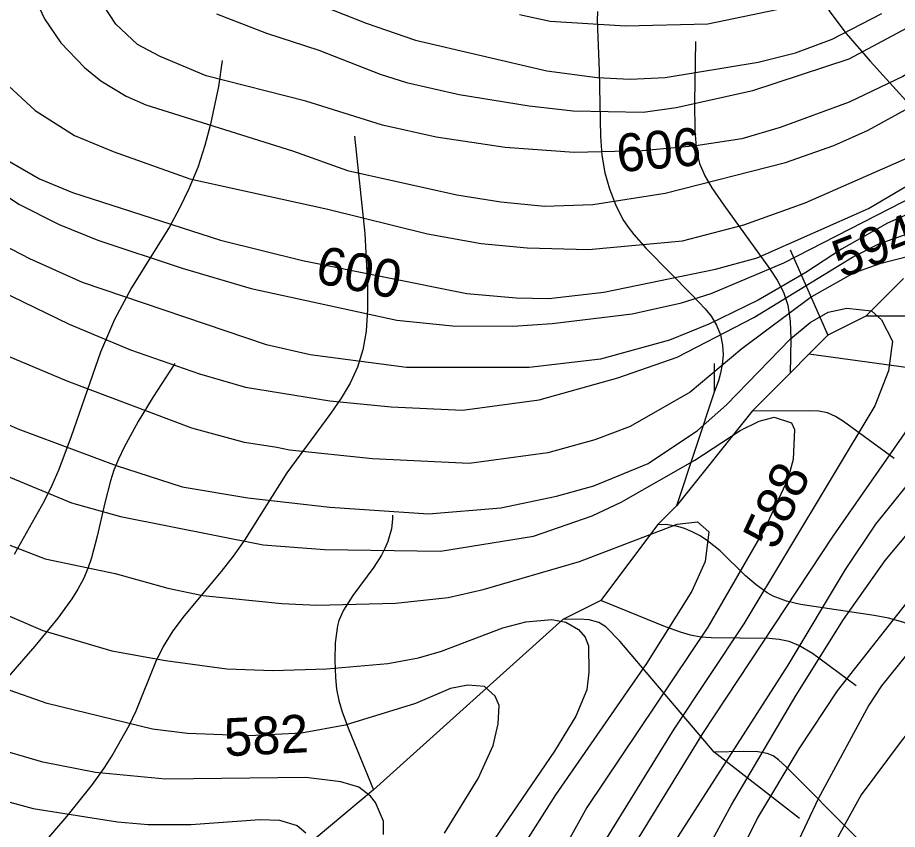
# Model space of a CAD drawing. Extents: x -709584 to -702006, y -1161789 to -1157496.
# Drawn here: x -708901 to -708668.6, y -1161172.4 to -1160958.2 of the extents above; entities that cross this region are included whole.
import ezdxf

# ---------------------------------------------------------------- set-up
doc = ezdxf.new("R2010")
doc.units = 0
for name, color, linetype in [('120_vrstevnice hlavní', 7, 'Continuous'), ('121_vrstevnice hlavní_popis', 7, 'Continuous'), ('122_vrstevnice základní', 7, 'Continuous'), ('411_akumulovaný odtok', 7, 'Continuous')]:
    doc.layers.add(name, color=color, linetype=linetype)

msp = doc.modelspace()

# ---------------------------------------------------------------- linework, layer by layer
at = {"layer": '120_vrstevnice hlavní'}
for points in [[(-708826.33, -1160952.72), (-708808.97, -1160959.66), (-708795.95, -1160964.15), (-708761.23, -1160972.25), (-708747.93, -1160973.98), (-708739.25, -1160974.41), (-708729.99, -1160973.98), (-708705.4, -1160969.93), (-708695.57, -1160967.47), (-708685.88, -1160963.86), (-708672.71, -1160957.06)], [(-708908.19, -1160993.22), (-708895.18, -1161000.74), (-708886.5, -1161004.36), (-708847.44, -1161016.94), (-708825.75, -1161022.29), (-708782.35, -1161030.97), (-708769.33, -1161032.13), (-708760.66, -1161032.27), (-708746.19, -1161030.68), (-708716.68, -1161024.61), (-708705.69, -1161021.57), (-708676.28, -1161008.53), (-708657.13, -1160997.28)], [(-708840.21, -1161084.92), (-708818.51, -1161087.38), (-708792.48, -1161089.12), (-708773.39, -1161087.53), (-708758.63, -1161084.49), (-708748.8, -1161081.74), (-708734.48, -1161075.81), (-708721.46, -1161067.13), (-708713.79, -1161060.33), (-708696.87, -1161042.98), (-708691.66, -1161038.64), (-708686.89, -1161035.89), (-708681.97, -1161034.88), (-708675.46, -1161035.6), (-708672.86, -1161037.91), (-708669.96, -1161043.55), (-708670.98, -1161051.36), (-708674.59, -1161060.62), (-708709.16, -1161118.19), (-708727.68, -1161145.96), (-708756.32, -1161192.25)], [(-708913.98, -1161060.91), (-708900.96, -1161066.7), (-708874.93, -1161076.39), (-708857.57, -1161082.03), (-708840.21, -1161084.92)], [(-708659.26, -1161117.76), (-708672.86, -1161134.54), (-708676.18, -1161139.6), (-708689.54, -1161164.31), (-708704.1, -1161195.14)], [(-708804.34, -1161173.73), (-708804.34, -1161170.26), (-708806.51, -1161165.34), (-708807.81, -1161163.61), (-708810.85, -1161161.29), (-708815.62, -1161159.85), (-708824.88, -1161158.69), (-708861.91, -1161159.12), (-708880.42, -1161157.39), (-708894.31, -1161154.64), (-708908.19, -1161150.59)]]:
    msp.add_lwpolyline(points, dxfattribs=at)
at = {"layer": '122_vrstevnice základní'}
for points in [[(-708621.94, -1160943.75), (-708641.76, -1160958.5), (-708667.22, -1160973.69), (-708681.39, -1160980.49), (-708699.62, -1160987.14), (-708709.74, -1160990.18), (-708721.89, -1160992.06), (-708736.07, -1160993.36), (-708754, -1160993.8), (-708772.23, -1160992.5), (-708790.45, -1160989.75), (-708804.63, -1160986.56), (-708824.88, -1160980.2), (-708851.2, -1160973.55), (-708863.35, -1160968.48), (-708869.28, -1160965.3), (-708875.07, -1160959.95), (-708878.25, -1160955.03)], [(-708848.46, -1160957.2), (-708835.29, -1160962.26), (-708821.41, -1160966.75), (-708805.21, -1160973.11), (-708798.26, -1160975.28), (-708784.38, -1160978.46), (-708765.86, -1160981.5), (-708754.29, -1160982.8), (-708735.78, -1160983.09), (-708727.1, -1160981.94), (-708706.85, -1160977.45), (-708681.39, -1160969.06), (-708661.14, -1160958.21), (-708639.16, -1160944.04)], [(-708896.77, -1160952.14), (-708893.87, -1160958.5), (-708889.53, -1160964.87), (-708883.32, -1160971.38), (-708878.98, -1160974.85), (-708872.32, -1160978.9), (-708867.12, -1160981.21), (-708828.35, -1160993.36), (-708813.89, -1160998.57), (-708784.96, -1161004.93), (-708773.39, -1161006.81), (-708761.81, -1161007.97), (-708749.08, -1161007.54), (-708729.99, -1161004.5), (-708698.17, -1160996.4), (-708685.44, -1160991.92), (-708676.33, -1160987.87), (-708659.55, -1160978.61), (-708645.23, -1160969.35), (-708624.69, -1160957.35)], [(-708903.42, -1160976.15), (-708896.33, -1160982.66), (-708885.92, -1160989.31), (-708875.79, -1160993.51), (-708855.54, -1161000.74), (-708819.09, -1161008.7), (-708792.77, -1161015.2), (-708778.59, -1161017.81), (-708766.44, -1161018.97), (-708750.24, -1161019.4), (-708725.36, -1161017.08), (-708709.16, -1161012.89), (-708692.96, -1161007.1), (-708666.78, -1160995.53), (-708647.4, -1160984.54), (-708610.52, -1160959.23), (-708602.42, -1160955.18)], [(-708768.47, -1160957.35), (-708760.37, -1160959.08), (-708740.41, -1160960.38), (-708718.71, -1160959.8), (-708700.48, -1160956.04)], [(-708575.95, -1160956.77), (-708574.21, -1160959.08), (-708572.04, -1160963.71), (-708571.03, -1160975.28), (-708573.34, -1160993.8), (-708581.44, -1161030.83), (-708586.5, -1161047.03), (-708593.59, -1161059.18), (-708599.09, -1161066.84), (-708615.72, -1161087.38), (-708651.16, -1161128.61), (-708667.62, -1161149.13), (-708678.21, -1161163.32), (-708687.61, -1161180.39)], [(-708889.97, -1161012.75), (-708879.84, -1161016.94), (-708857.57, -1161024.32), (-708839.34, -1161029.67), (-708800.87, -1161038.06), (-708786.11, -1161039.5), (-708770.2, -1161039.65), (-708759.79, -1161038.93), (-708738.67, -1161036.32), (-708725.65, -1161033.43), (-708717.84, -1161030.97), (-708698.6, -1161022.87), (-708635.97, -1160990.76)], [(-708917.02, -1160996.4), (-708900.67, -1161007.39), (-708889.97, -1161012.75)], [(-708644.07, -1161000.45), (-708671.27, -1161012.46), (-708683.42, -1161019.25), (-708692.82, -1161025.47), (-708705.4, -1161032.71), (-708718.42, -1161039.07), (-708728.83, -1161043.27), (-708747.06, -1161048.33), (-708765.86, -1161050.5), (-708798.26, -1161050.5), (-708823.72, -1161047.17), (-708835.29, -1161044.57), (-708883.89, -1161028.08), (-708897.78, -1161021.86), (-708913.98, -1161013.47)], [(-708887.37, -1161039.07), (-708871.17, -1161045.87), (-708852.94, -1161052.23), (-708840.79, -1161055.71), (-708818.51, -1161059.32), (-708802.31, -1161060.91), (-708783.51, -1161061.78), (-708763.26, -1161059.03), (-708742.43, -1161053.25), (-708726.81, -1161047.75), (-708706.56, -1161037.33), (-708680.52, -1161021.42), (-708673.73, -1161017.95), (-708658.54, -1161012.6)], [(-708665.34, -1161021.13), (-708673.29, -1161023.16), (-708680.23, -1161025.62), (-708691.37, -1161031.84), (-708709.74, -1161045.58), (-708723.34, -1161057.01), (-708739.25, -1161066.12), (-708748.51, -1161069.59), (-708760.95, -1161073.06), (-708781.77, -1161075.81), (-708807.23, -1161074.65), (-708829.22, -1161072.34), (-708832.54, -1161071.62), (-708841.08, -1161070.31), (-708854.96, -1161066.55), (-708887.94, -1161054.11), (-708922.66, -1161039.5)], [(-708908.63, -1161028.8), (-708887.37, -1161039.07)], [(-708685.58, -1161095.05), (-708653.19, -1161048.62)], [(-708953.18, -1161051.8), (-708934.52, -1161064.96), (-708925.84, -1161070.02), (-708886.79, -1161086.22), (-708873.77, -1161089.84), (-708836.16, -1161097.36), (-708819.96, -1161098.52), (-708789.3, -1161098.95), (-708764.71, -1161095.05), (-708749.23, -1161089.7), (-708741.56, -1161086.08), (-708722.18, -1161074.94), (-708710.18, -1161067.13), (-708705.11, -1161064.67), (-708701.21, -1161063.66), (-708696.58, -1161065.11), (-708695.86, -1161066.84), (-708696.15, -1161074.8), (-708697.59, -1161080.01), (-708703.67, -1161093.02), (-708718.71, -1161119.06), (-708750.68, -1161166.65), (-708757.04, -1161178.07)], [(-708723.48, -1161186.17), (-708712.49, -1161165.92), (-708695.42, -1161137), (-708682.84, -1161117.03), (-708671.84, -1161101.41), (-708643.93, -1161068.14), (-708634.24, -1161055.13)], [(-708646.82, -1161057.58), (-708674.45, -1161091.86), (-708682.4, -1161103.87), (-708697.59, -1161129.04), (-708733.32, -1161184.73)], [(-708905.88, -1161096.35), (-708893.73, -1161100.98), (-708875.21, -1161104.88), (-708861.33, -1161108.79), (-708852.07, -1161110.67), (-708831.24, -1161112.84), (-708821.99, -1161113.27), (-708801.16, -1161112.7), (-708787.27, -1161111.25), (-708778.01, -1161109.08), (-708752.56, -1161101.7), (-708726.81, -1161091.87), (-708721.46, -1161091.29), (-708718.42, -1161093.89), (-708719.43, -1161101.7), (-708722.9, -1161109.51), (-708734.91, -1161128.61), (-708758.92, -1161163.32), (-708781.05, -1161198.03)], [(-708739.25, -1161178.36), (-708720.01, -1161147.12), (-708685.58, -1161095.05)], [(-708931.05, -1161104.16), (-708894.31, -1161119.93), (-708876.08, -1161125.28), (-708861.91, -1161127.88), (-708845.71, -1161130.05), (-708833.56, -1161130.49), (-708819.38, -1161130.05), (-708803.18, -1161128.61), (-708795.08, -1161127.16), (-708789.01, -1161125.42), (-708772.81, -1161119.2), (-708766.73, -1161117.61), (-708759.93, -1161117.03), (-708756.17, -1161117.76), (-708752.84, -1161119.64), (-708751.11, -1161121.66), (-708750.24, -1161123.98), (-708750.1, -1161130.92), (-708750.68, -1161135.55), (-708753.57, -1161142.49), (-708759.21, -1161151.75), (-708797.11, -1161207.29)], [(-708660.71, -1161105.61), (-708684.57, -1161135.84), (-708694.7, -1161151.17), (-708705.55, -1161169.4), (-708714.66, -1161187.62)], [(-708788.28, -1161173.45), (-708779.32, -1161158.98), (-708775.41, -1161150.3), (-708774.11, -1161144.52), (-708773.82, -1161139.74), (-708774.83, -1161137.28), (-708777.72, -1161134.68), (-708782.06, -1161134.39), (-708786.69, -1161135.26), (-708795.95, -1161139.16), (-708814.46, -1161144.95), (-708826.04, -1161146.98), (-708839.92, -1161147.7), (-708856.12, -1161147.12), (-708865.38, -1161145.96), (-708893.15, -1161139.16), (-708904.72, -1161135.11)], [(-708944.35, -1161147.7), (-708935.39, -1161152.62), (-708925.26, -1161157.25), (-708907.04, -1161164.19), (-708896.91, -1161166.94), (-708874.64, -1161170.41), (-708866.54, -1161171.13), (-708855.25, -1161171.13), (-708837.03, -1161169.83), (-708831.82, -1161169.97), (-708827.19, -1161171.42), (-708824.88, -1161173.3)]]:
    msp.add_lwpolyline(points, dxfattribs=at)
at = {"layer": '411_akumulovaný odtok'}
for p, q in [((-708696.99, -1161019.5), (-708686.99, -1161042)), ((-708666.99, -1161027), (-708676.99, -1161037)), ((-708676.99, -1161037), (-708686.99, -1161042)), ((-708661.99, -1161037), (-708676.99, -1161037)), ((-708686.99, -1161042), (-708691.99, -1161047)), ((-708691.99, -1161047), (-708696.99, -1161052)), ((-708716.99, -1161049.5), (-708716.99, -1161057)), ((-708696.99, -1161052), (-708706.99, -1161062)), ((-708716.99, -1161057), (-708726.99, -1161087)), ((-708706.99, -1161062), (-708726.99, -1161087)), ((-708726.99, -1161087), (-708731.99, -1161092)), ((-708731.99, -1161092), (-708746.99, -1161112)), ((-708746.99, -1161112), (-708756.99, -1161117)), ((-708756.99, -1161117), (-708806.99, -1161162)), ((-708694.49, -1161169.5), (-708716.99, -1161152)), ((-708806.99, -1161162), (-708836.99, -1161187))]:
    msp.add_line(p, q, dxfattribs=at)
for points in [[(-708691.99, -1160919.5), (-708692.27, -1160933.66), (-708691.88, -1160942.33), (-708691.05, -1160946.83), (-708690.4, -1160948.89), (-708688.67, -1160952.88), (-708686.5, -1160956.67), (-708682.21, -1160962.39), (-708675.86, -1160969.67), (-708659.53, -1160987.61), (-708654.89, -1160993.01), (-708652.21, -1160996.63), (-708651.12, -1160998.45), (-708650.31, -1161000.28), (-708649.89, -1161002.13), (-708650.03, -1161004.02), (-708650.74, -1161006.17), (-708651.9, -1161008.49), (-708655.02, -1161013.28), (-708661.99, -1161022)], [(-708747.85, -1160956.61), (-708747.9, -1160958.98), (-708747.37, -1160972.11), (-708747.08, -1160989.56), (-708746.7, -1160994.51), (-708745.91, -1160999.13), (-708744.71, -1161003.4), (-708743.13, -1161007.52), (-708741.11, -1161011.42), (-708739.76, -1161013.44), (-708738.27, -1161015.38), (-708735.01, -1161019.1), (-708722.71, -1161031.51), (-708719.37, -1161035.07), (-708717.82, -1161037.01), (-708716.45, -1161039.31), (-708715.4, -1161041.89), (-708714.8, -1161044.64), (-708714.69, -1161047.2), (-708714.91, -1161049.69), (-708715.34, -1161051.99), (-708715.88, -1161054), (-708716.99, -1161057)], [(-708721.99, -1160964.5), (-708722.24, -1160980.47), (-708722.18, -1160988.04), (-708721.72, -1160993.31), (-708720.94, -1160996.67), (-708719.5, -1160999.95), (-708717.63, -1161003.09), (-708714.49, -1161007.69), (-708702.42, -1161024.4), (-708700.42, -1161027.49), (-708698.7, -1161030.68), (-708697.55, -1161034.05), (-708696.99, -1161038.29), (-708696.82, -1161043.05), (-708696.99, -1161052)], [(-708846.99, -1160969.5), (-708847.97, -1160976.4), (-708850.01, -1160986.26), (-708851.53, -1160991.93), (-708853.42, -1160997.7), (-708855.74, -1161003.39), (-708858.29, -1161008.68), (-708860.9, -1161013.37), (-708870.91, -1161029.51), (-708875.38, -1161037.83), (-708879.06, -1161046.46), (-708886.86, -1161068.69), (-708890.14, -1161077.44), (-708891.94, -1161081.69), (-708893.93, -1161085.83), (-708901.89, -1161099.87)], [(-708811.99, -1160989.5), (-708809.31, -1161015.11), (-708808.56, -1161028.76), (-708808.57, -1161035.2), (-708808.97, -1161040.97), (-708809.83, -1161045.87), (-708811.23, -1161050.42), (-708813.17, -1161054.62), (-708815.56, -1161058.65), (-708818.26, -1161062.6), (-708829.85, -1161078.34), (-708841.1, -1161096.05), (-708844.08, -1161100.31), (-708847.24, -1161104.35), (-708857.01, -1161116.04), (-708859.98, -1161120.03), (-708862.57, -1161124.19), (-708864.59, -1161128.3), (-708869.78, -1161141.22), (-708871.6, -1161145.08), (-708875.83, -1161152.6), (-708878.22, -1161156.26), (-708881.3, -1161160.56), (-708887.96, -1161168.93), (-708895.04, -1161177.1)], [(-708624.49, -1161074.5), (-708649.72, -1161056.9), (-708653.39, -1161054.55), (-708657.23, -1161052.61), (-708661.38, -1161051.42), (-708665.69, -1161050.64), (-708691.99, -1161047)], [(-708859.49, -1161049.5), (-708865.18, -1161058.29), (-708869.11, -1161064.76), (-708872.83, -1161071.51), (-708874.36, -1161074.69), (-708875.54, -1161077.59), (-708876.46, -1161080.43), (-708877.95, -1161086.24), (-708879.95, -1161095.03), (-708881.5, -1161100.77), (-708882.45, -1161103.56), (-708883.59, -1161106.26), (-708885.04, -1161108.98), (-708886.69, -1161111.61), (-708890.39, -1161116.68), (-708896.46, -1161124.04), (-708946.99, -1161182)], [(-708669.49, -1161074.5), (-708682.92, -1161064.81), (-708684.98, -1161063.48), (-708687.13, -1161062.46), (-708689.4, -1161062.04), (-708691.76, -1161061.92), (-708706.99, -1161062)], [(-708801.99, -1161089.5), (-708801.94, -1161090.55), (-708802.25, -1161093.09), (-708803.23, -1161096.48), (-708804.01, -1161098.29), (-708804.92, -1161100.06), (-708806.87, -1161103.17), (-708812.45, -1161110.72), (-708814.91, -1161114.59), (-708816.13, -1161117.32), (-708816.52, -1161118.73), (-708817.09, -1161123.17), (-708817.21, -1161127.74), (-708817.07, -1161132.33), (-708816.78, -1161135.37), (-708816.19, -1161138.39), (-708815.29, -1161141.39), (-708813.64, -1161145.84), (-708806.99, -1161162)], [(-708644.49, -1161129.5), (-708659.88, -1161120.87), (-708663.58, -1161119.09), (-708667.22, -1161117.69), (-708670.97, -1161116.71), (-708674.81, -1161115.99), (-708694.21, -1161113.09), (-708697.93, -1161112.21), (-708701.44, -1161110.89), (-708703, -1161110.02), (-708705.94, -1161107.89), (-708708.72, -1161105.46), (-708715.46, -1161098.94), (-708718.8, -1161096.24), (-708720.76, -1161094.97), (-708722.8, -1161093.87), (-708724.88, -1161093.01), (-708726.67, -1161092.49), (-708729.78, -1161091.99), (-708731.99, -1161092)], [(-708679.49, -1161134.5), (-708691.09, -1161126.01), (-708694.71, -1161123.86), (-708697.24, -1161122.82), (-708699.85, -1161122.29), (-708702.55, -1161122.06), (-708717.79, -1161121.89), (-708720.53, -1161121.66), (-708723.24, -1161121.16), (-708725.92, -1161120.39), (-708729.9, -1161118.95), (-708746.99, -1161112)], [(-708716.99, -1161152), (-708741.96, -1161122.77), (-708745.68, -1161118.93), (-708747.46, -1161117.78), (-708750, -1161117.14), (-708752.81, -1161116.93), (-708756.99, -1161117)], [(-708679.49, -1161174.5), (-708697.98, -1161155.89), (-708700.03, -1161154.05), (-708701.47, -1161153.02), (-708703.01, -1161152.35), (-708705.49, -1161151.93), (-708709.16, -1161151.84), (-708716.99, -1161152)]]:
    msp.add_lwpolyline(points, dxfattribs=at)

# ---------------------------------------------------------------- texts
at = {"layer": '121_vrstevnice hlavní_popis'}
for s, rotation, p in [('606', 5.076, (-708742.39, -1160999.01)), ('594', 21.2571, (-708683.32, -1161027.03)), ('600', 348.5504, (-708822.7, -1161028.07)), ('588', 65.2916, (-708700.75, -1161099.02)), ('582', 2.8702, (-708846.24, -1161153.14))]:
    msp.add_text(s, height=10, rotation=rotation, dxfattribs=at).set_placement(p)

doc.saveas('drawing.dxf')
